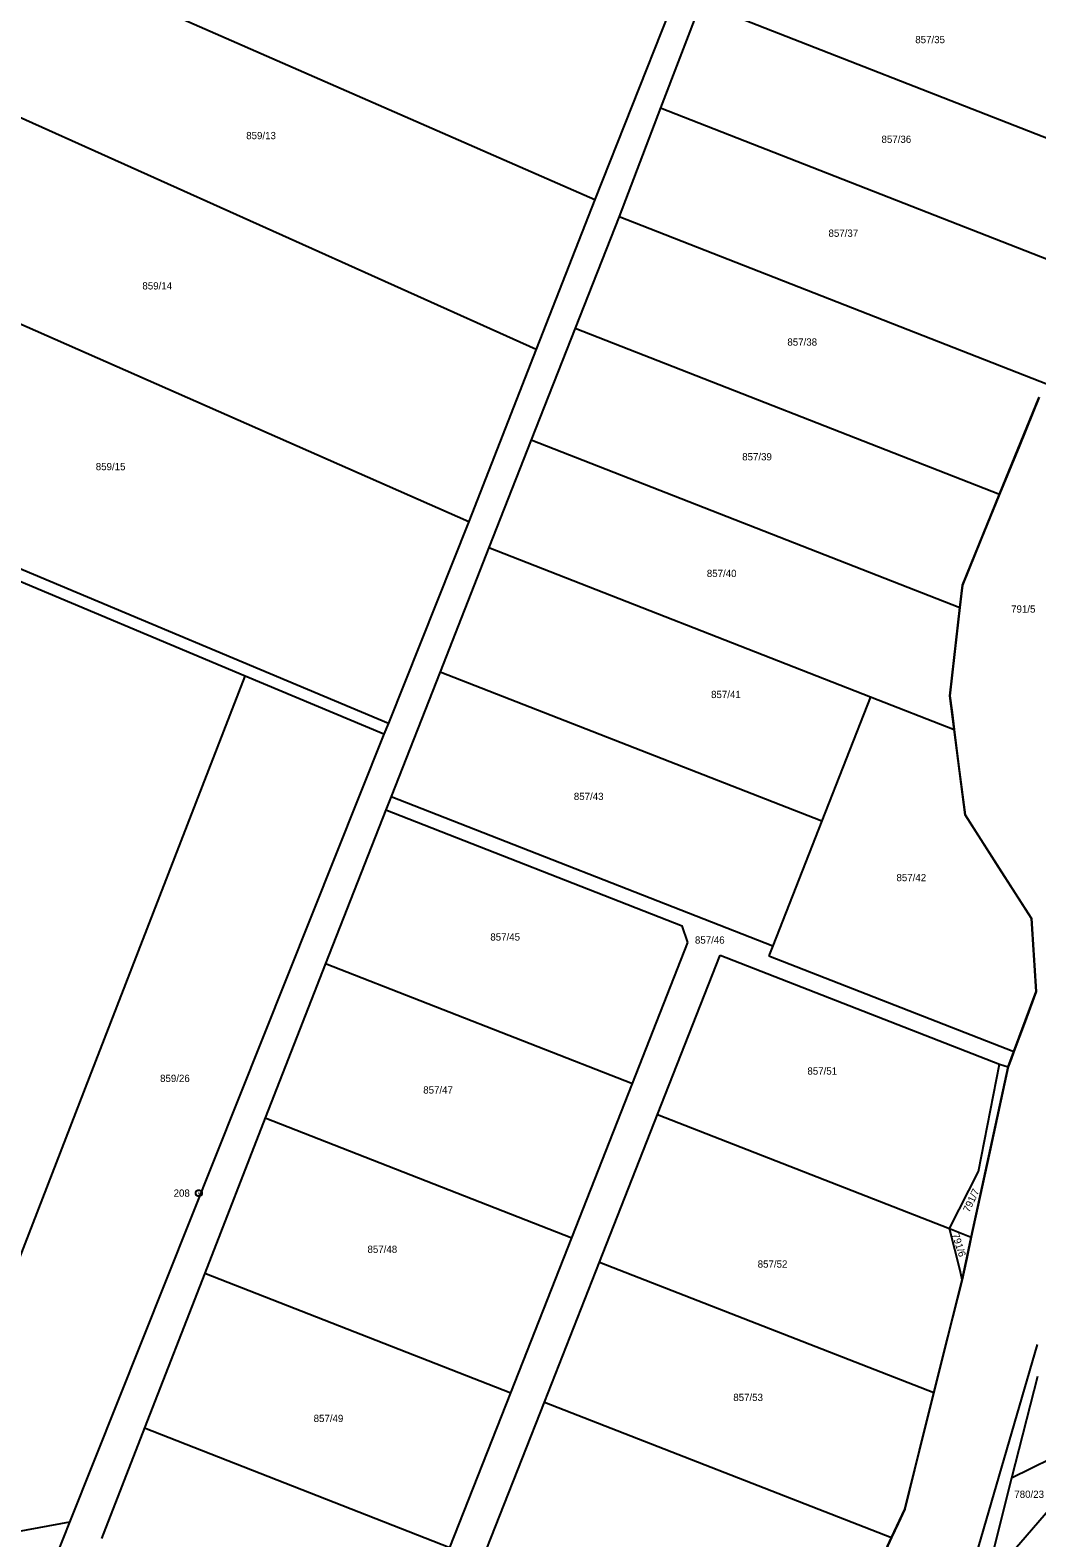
# Model space of a CAD drawing. Extents: x -593358 to -590116, y -1072518 to -1068420.
# Drawn here: x -592265.8 to -592030.1, y -1070910.9 to -1070557.8 of the extents above; entities that cross this region are included whole.
import ezdxf

# ---------------------------------------------------------------- set-up
doc = ezdxf.new("R2010")
doc.units = 0
for name, color, linetype in [('Parcela KN', 7, 'Continuous'), ('Parcela ZE', 7, 'Continuous'), ('Parcelní číslo', 7, 'Continuous'), ('Vnitřní obvod', 7, 'Continuous'), ('Vrstva 17', 7, 'Continuous'), ('Vrstva 24', 7, 'Continuous')]:
    doc.layers.add(name, color=color, linetype=linetype)

msp = doc.modelspace()

# ---------------------------------------------------------------- linework, layer by layer
at = {"layer": 'Parcela KN'}
for p, q in [((-592108.76, -1070551.35), (-592118.18, -1070575.98)), ((-592116.27, -1070553.74), (-592133.59, -1070597.42)), ((-592118.18, -1070575.98), (-592127.9, -1070601.4)), ((-592133.59, -1070597.42), (-592147.29, -1070632.48)), ((-592127.9, -1070601.4), (-592138.18, -1070627.58)), ((-592138.18, -1070627.58), (-592148.46, -1070653.73)), ((-592147.29, -1070632.48), (-592163.07, -1070672.85)), ((-592038.8, -1070666.46), (-592029.5, -1070643.75)), ((-592148.46, -1070653.73), (-592158.37, -1070678.94)), ((-592047.5, -1070687.74), (-592038.8, -1070666.46)), ((-592163.07, -1070672.85), (-592181.89, -1070720.08)), ((-592158.37, -1070678.94), (-592169.81, -1070708.03)), ((-592048.09, -1070692.99), (-592047.5, -1070687.74)), ((-592050.43, -1070713.65), (-592048.09, -1070692.99)), ((-592169.81, -1070708.03), (-592181.28, -1070737.23)), ((-592049.43, -1070721.55), (-592050.43, -1070713.65)), ((-592181.89, -1070720.08), (-592182.94, -1070722.69)), ((-592046.89, -1070741.56), (-592049.43, -1070721.55)), ((-592182.94, -1070722.69), (-592256.56, -1070907.2)), ((-592181.28, -1070737.23), (-592182.53, -1070740.4)), ((-592182.53, -1070740.4), (-592196.62, -1070776.34)), ((-592031.32, -1070765.86), (-592046.89, -1070741.56)), ((-592030.21, -1070782.95), (-592031.32, -1070765.86)), ((-592196.62, -1070776.34), (-592210.72, -1070812.54)), ((-592035.45, -1070796.99), (-592030.21, -1070782.95)), ((-592036.78, -1070800.54), (-592035.45, -1070796.99)), ((-592043.73, -1070825.07), (-592038.8, -1070799.93)), ((-592038.8, -1070799.93), (-592036.78, -1070800.54)), ((-592210.72, -1070812.54), (-592224.88, -1070848.89)), ((-592050.49, -1070838.44), (-592043.73, -1070825.07)), ((-592048.06, -1070848.26), (-592050.49, -1070838.44)), ((-592047.58, -1070850.42), (-592048.06, -1070848.26)), ((-592224.88, -1070848.89), (-592238.99, -1070885.13)), ((-592054.19, -1070876.86), (-592047.58, -1070850.42)), ((-592044.25, -1070914.9), (-592029.91, -1070865.59)), ((-592029.94, -1070873.08), (-592035.98, -1070896.91)), ((-592061.02, -1070904.16), (-592054.19, -1070876.86)), ((-592006.31, -1070882.3), (-592035.98, -1070896.91)), ((-592238.99, -1070885.13), (-592249.08, -1070911.03)), ((-592035.98, -1070896.91), (-592041.08, -1070917.09)), ((-592022.86, -1070899.35), (-592039.31, -1070918.31)), ((-592064.12, -1070910.82), (-592061.02, -1070904.16)), ((-592256.56, -1070907.2), (-592268.84, -1070909.47)), ((-592256.56, -1070907.2), (-592259.57, -1070914.74)), ((-592082.11, -1070949.99), (-592064.12, -1070910.82))]:
    msp.add_line(p, q, dxfattribs=at)
at = {"layer": 'Parcela ZE'}
for p, q in [((-592287.82, -1070529.87), (-592133.59, -1070597.42)), ((-592108.76, -1070551.35), (-592003.07, -1070592.7)), ((-592301.27, -1070563.29), (-592147.29, -1070632.48)), ((-592118.18, -1070575.98), (-592012.89, -1070617.17)), ((-592331.18, -1070598.75), (-592163.07, -1070672.85)), ((-592127.9, -1070601.4), (-592027.56, -1070640.66)), ((-592138.18, -1070627.58), (-592038.8, -1070666.46)), ((-592148.46, -1070653.73), (-592048.09, -1070692.99)), ((-592283.57, -1070677.37), (-592181.89, -1070720.08)), ((-592158.37, -1070678.94), (-592069, -1070713.89)), ((-592215.43, -1070709.05), (-592277.7, -1070682.92)), ((-592251.88, -1070803.07), (-592215.43, -1070709.05)), ((-592182.94, -1070722.69), (-592215.43, -1070709.05)), ((-592169.81, -1070708.03), (-592080.43, -1070742.98)), ((-592069, -1070713.89), (-592080.43, -1070742.98)), ((-592069, -1070713.89), (-592049.43, -1070721.55)), ((-592181.28, -1070737.23), (-592091.91, -1070772.19)), ((-592182.53, -1070740.4), (-592113.11, -1070767.56)), ((-592080.43, -1070742.98), (-592091.91, -1070772.19)), ((-592111.77, -1070771.42), (-592113.11, -1070767.56)), ((-592124.76, -1070804.45), (-592111.77, -1070771.42)), ((-592118.9, -1070811.72), (-592104.22, -1070774.38)), ((-592104.22, -1070774.38), (-592038.8, -1070799.93)), ((-592091.91, -1070772.19), (-592092.84, -1070774.54)), ((-592092.84, -1070774.54), (-592035.45, -1070796.99)), ((-592196.62, -1070776.34), (-592124.76, -1070804.45)), ((-592045.42, -1070840.42), (-592036.78, -1070800.54)), ((-592288.8, -1070898.3), (-592251.88, -1070803.07)), ((-592138.97, -1070840.6), (-592124.76, -1070804.45)), ((-592210.72, -1070812.54), (-592138.97, -1070840.6)), ((-592132.49, -1070846.29), (-592118.9, -1070811.72)), ((-592118.9, -1070811.72), (-592050.49, -1070838.44)), ((-592153.25, -1070876.91), (-592138.97, -1070840.6)), ((-592050.49, -1070838.44), (-592045.42, -1070840.42)), ((-592047.58, -1070850.42), (-592045.42, -1070840.42)), ((-592145.39, -1070879.09), (-592132.49, -1070846.29)), ((-592132.49, -1070846.29), (-592054.19, -1070876.86)), ((-592224.88, -1070848.89), (-592153.25, -1070876.91)), ((-592167.49, -1070913.11), (-592153.25, -1070876.91)), ((-592161.16, -1070919.2), (-592145.39, -1070879.09)), ((-592145.39, -1070879.09), (-592064.12, -1070910.82)), ((-592238.99, -1070885.13), (-592167.49, -1070913.11))]:
    msp.add_line(p, q, dxfattribs=at)
at = {"layer": 'Vnitřní obvod'}
for points in [[(-592029.5, -1070643.75), (-592034.15, -1070655.105), (-592038.8, -1070666.46), (-592043.15, -1070677.1), (-592047.5, -1070687.74), (-592047.795, -1070690.365), (-592048.09, -1070692.99), (-592049.26, -1070703.32), (-592050.43, -1070713.65), (-592049.93, -1070717.6), (-592049.43, -1070721.55), (-592048.16, -1070731.555), (-592046.89, -1070741.56), (-592039.105, -1070753.71), (-592031.32, -1070765.86), (-592030.765, -1070774.405), (-592030.21, -1070782.95), (-592032.83, -1070789.97), (-592035.45, -1070796.99), (-592036.115, -1070798.765), (-592036.78, -1070800.54)], [(-592036.78, -1070800.54), (-592041.1, -1070820.48), (-592045.42, -1070840.42), (-592046.5, -1070845.42), (-592047.58, -1070850.42), (-592050.885, -1070863.64), (-592054.19, -1070876.86), (-592057.605, -1070890.51), (-592061.02, -1070904.16), (-592062.57, -1070907.49), (-592064.12, -1070910.82), (-592073.115, -1070930.405)]]:
    msp.add_lwpolyline(points, dxfattribs=at)
at = {"layer": 'Vrstva 24'}
msp.add_line((-592226.34, -1070830.14), (-592226.24, -1070830.14), dxfattribs=at)
msp.add_lwpolyline([(-592226.1, -1070829.42), (-592225.76, -1070829.61), (-592225.57, -1070829.95), (-592225.57, -1070830.34), (-592225.76, -1070830.68), (-592226.1, -1070830.87), (-592226.49, -1070830.87), (-592226.83, -1070830.68), (-592227.02, -1070830.34), (-592227.02, -1070829.95), (-592226.83, -1070829.61), (-592226.49, -1070829.42)], close=True, dxfattribs=at)

# ---------------------------------------------------------------- texts
at = {"layer": 'Parcelní číslo'}
for s, p in [('857/35', (-592058.54, -1070560.82)), ('859/13', (-592215.195, -1070583.3)), ('857/36', (-592066.443, -1070584.17)), ('857/37', (-592078.853, -1070606.16)), ('859/14', (-592239.498, -1070618.5)), ('857/38', (-592088.483, -1070631.66)), ('857/39', (-592099.063, -1070658.53)), ('859/15', (-592250.415, -1070660.83)), ('857/40', (-592107.343, -1070685.85)), ('791/5', (-592036.092, -1070694.19)), ('857/41', (-592106.348, -1070714.2)), ('857/43', (-592138.483, -1070738.08)), ('857/42', (-592062.94, -1070757.09)), ('857/45', (-592158.033, -1070771)), ('857/46', (-592110.126, -1070771.71)), ('859/26', (-592235.36, -1070804.11)), ('857/51', (-592083.795, -1070802.39)), ('857/47', (-592173.746, -1070806.83)), ('857/48', (-592186.796, -1070844.14)), ('857/52', (-592095.436, -1070847.6)), ('857/53', (-592101.15, -1070878.83)), ('857/49', (-592199.406, -1070883.76)), ('780/23', (-592035.346, -1070901.52))]:
    msp.add_text(s, height=1.7, dxfattribs=at).set_placement(p)
for s, rotation, p in [('791/7', 64.80153, (-592045.909, -1070834.779)), ('791/6', 287.7967, (-592049.981, -1070839.821))]:
    msp.add_text(s, height=1.7, rotation=rotation, dxfattribs=at).set_placement(p)
at = {"layer": 'Vrstva 17'}
msp.add_text('208', height=1.7, dxfattribs=at).set_placement((-592232.191, -1070830.99))

doc.saveas('drawing.dxf')
